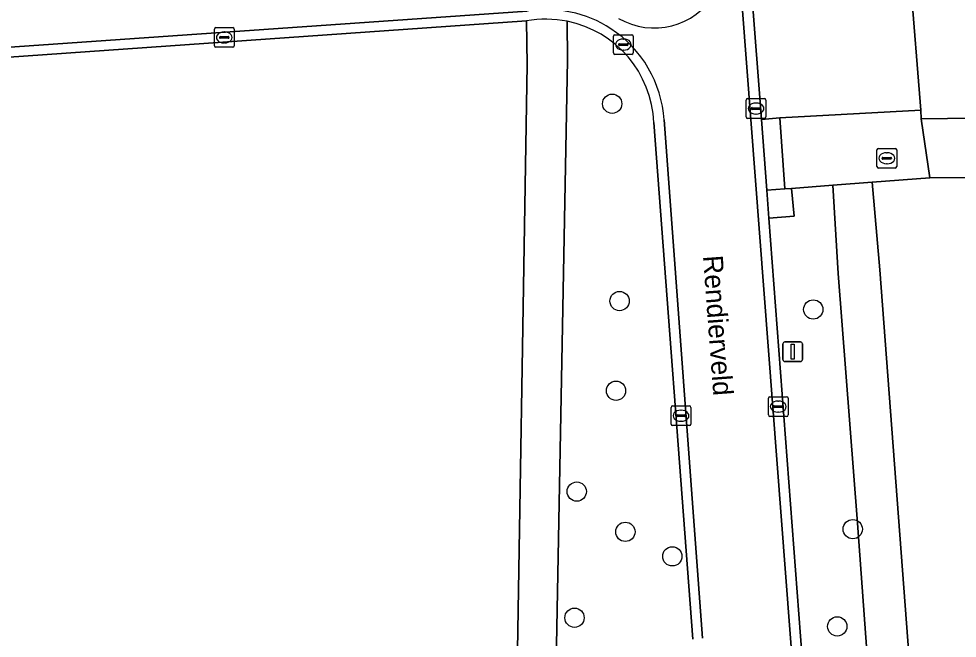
# Model space of a CAD drawing. Extents: x 162661 to 163484, y 380247 to 381230.
# Drawn here: x 163101.01 to 163148.58, y 380368.43 to 380399.85 of the extents above; entities that cross this region are included whole.
import ezdxf

# ---------------------------------------------------------------- set-up
doc = ezdxf.new("R2010")
doc.units = 0
for name, color, linetype in [('IMGEO_Berm_halfverhard', 7, 'Continuous'), ('IMGEO_Boom', 7, 'Continuous'), ('IMGEO_Erf', 7, 'Continuous'), ('IMGEO_Groenvoorziening', 7, 'Continuous'), ('IMGEO_Kolk', 7, 'Continuous'), ('IMGEO_Lichtmast', 7, 'Continuous'), ('IMGEO_Openbare_ruimte_label', 7, 'Continuous'), ('IMGEO_Parkeervlak_open', 7, 'Continuous'), ('IMGEO_Rijbaan_lokaal_gesloten', 7, 'Continuous'), ('IMGEO_Rijbaan_lokaal_open', 7, 'Continuous'), ('IMGEO_Rioolput', 7, 'Continuous'), ('IMGEO_Voetpad_open', 7, 'Continuous')]:
    doc.layers.add(name, color=color, linetype=linetype)

msp = doc.modelspace()

# ---------------------------------------------------------------- linework, layer by layer
at = {"layer": 'IMGEO_Berm_halfverhard'}
msp.add_lwpolyline([(163140.187, 380391.241), (163139.844, 380391.229), (163138.932, 380391.167), (163139.036, 380389.731), (163140.315, 380389.838)], close=True, dxfattribs=at)
at = {"layer": 'IMGEO_Boom'}
for centre in [(163131.093, 380395.542), (163131.467, 380385.535), (163141.285, 380385.108), (163131.287, 380380.986), (163129.297, 380375.871), (163131.762, 380373.827), (163143.288, 380373.966), (163134.141, 380372.586), (163129.184, 380369.472), (163142.501, 380369.033)]:
    msp.add_circle(centre, 0.489, dxfattribs=at)
at = {"layer": 'IMGEO_Erf'}
msp.add_lwpolyline([(163216.077, 380392.021), (163204.133, 380392.177), (163149.068, 380391.797), (163147.198, 380391.781), (163144.279, 380391.558), (163144.662, 380387.12), (163147.688, 380347.017), (163151.219, 380347.51), (163195.797, 380353.729), (163196.176, 380351.492), (163147.848, 380344.668), (163150.86, 380303.331), (163146.437, 380298.781)], dxfattribs=at)
at = {"layer": 'IMGEO_Groenvoorziening'}
for points in [[(163196.751, 380415.969), (163148.204, 380409.24), (163145.637, 380408.848), (163145.683, 380408.287), (163146.741, 380395.215), (163146.749, 380394.77), (163148.083, 380394.795), (163199.027, 380395.185)], [(163071.431, 380357.843), (163126.19, 380361.661), (163126.78, 380397.532), (163126.755, 380399.742), (163064.909, 380395.406)], [(163128.81, 380399.724), (163128.82, 380397.751), (163128.149, 380361.798), (163129.108, 380361.865)], [(163135.179, 380368.38), (163133.202, 380394.584)]]:
    msp.add_lwpolyline(points, dxfattribs=at)
msp.add_lwpolyline([(163142.548, 380386.928), (163142.283, 380391.415), (163140.187, 380391.241), (163140.315, 380389.838), (163139.036, 380389.731), (163142.33, 380346.217), (163145.542, 380346.659), (163143.52, 380374.274)], close=True, dxfattribs=at)
msp.add_arc((163127.737, 380394.36), 5.47, 2.3433, 78.6828, dxfattribs=at)
at = {"layer": 'IMGEO_Kolk'}
for p, q in [((163110.929, 380398.478), (163110.929, 380399.33)), ((163111.004, 380399.404), (163111.856, 380399.404)), ((163111.417, 380399.184), (163111.442, 380399.184)), ((163111.93, 380399.33), (163111.93, 380398.478)), ((163131.232, 380399.045), (163132.084, 380399.045)), ((163111.188, 380398.898), (163111.188, 380398.91)), ((163111.626, 380398.861), (163111.228, 380398.861)), ((163111.231, 380398.947), (163111.629, 380398.947)), ((163111.44, 380398.624), (163111.415, 380398.624)), ((163111.672, 380398.91), (163111.672, 380398.898)), ((163131.157, 380398.119), (163131.157, 380398.971)), ((163131.416, 380398.539), (163131.416, 380398.551)), ((163131.459, 380398.588), (163131.857, 380398.588)), ((163131.645, 380398.825), (163131.67, 380398.825)), ((163131.9, 380398.551), (163131.9, 380398.539)), ((163132.158, 380398.971), (163132.158, 380398.119)), ((163111.856, 380398.404), (163111.004, 380398.404)), ((163131.854, 380398.502), (163131.456, 380398.502)), ((163131.668, 380398.265), (163131.643, 380398.265)), ((163132.084, 380398.045), (163131.232, 380398.045)), ((163137.883, 380394.874), (163137.883, 380395.726)), ((163137.958, 380395.8), (163138.81, 380395.8)), ((163138.884, 380395.726), (163138.884, 380394.874)), ((163138.142, 380395.294), (163138.142, 380395.306)), ((163138.58, 380395.257), (163138.182, 380395.257)), ((163138.185, 380395.343), (163138.583, 380395.343)), ((163138.371, 380395.58), (163138.396, 380395.58)), ((163138.626, 380395.306), (163138.626, 380395.294)), ((163138.81, 380394.8), (163137.958, 380394.8)), ((163138.394, 380395.02), (163138.369, 380395.02)), ((163139.009, 380379.756), (163139.009, 380380.608)), ((163139.084, 380380.682), (163139.936, 380380.682)), ((163140.01, 380380.608), (163140.01, 380379.756)), ((163134.082, 380379.291), (163134.082, 380380.143)), ((163134.157, 380380.217), (163135.009, 380380.217)), ((163134.57, 380379.997), (163134.595, 380379.997)), ((163135.083, 380380.143), (163135.083, 380379.291)), ((163139.268, 380380.176), (163139.268, 380380.188)), ((163139.706, 380380.139), (163139.308, 380380.139)), ((163139.311, 380380.225), (163139.709, 380380.225)), ((163139.497, 380380.462), (163139.522, 380380.462)), ((163139.752, 380380.188), (163139.752, 380380.176)), ((163134.341, 380379.711), (163134.341, 380379.723)), ((163134.779, 380379.674), (163134.381, 380379.674)), ((163134.384, 380379.76), (163134.782, 380379.76)), ((163134.825, 380379.723), (163134.825, 380379.711)), ((163139.936, 380379.682), (163139.084, 380379.682)), ((163139.52, 380379.902), (163139.495, 380379.902)), ((163135.009, 380379.217), (163134.157, 380379.217)), ((163134.593, 380379.437), (163134.568, 380379.437))]:
    msp.add_line(p, q, dxfattribs=at)
for points in [[(163110.929, 380398.478), (163110.929, 380399.33)], [(163111.004, 380399.404), (163111.856, 380399.404)], [(163111.93, 380399.33), (163111.93, 380398.478)], [(163131.232, 380399.045), (163132.084, 380399.045)], [(163131.157, 380398.119), (163131.157, 380398.971)], [(163132.158, 380398.971), (163132.158, 380398.119)], [(163111.856, 380398.404), (163111.004, 380398.404)], [(163132.084, 380398.045), (163131.232, 380398.045)], [(163137.883, 380394.874), (163137.883, 380395.726)], [(163137.958, 380395.8), (163138.81, 380395.8)], [(163138.884, 380395.726), (163138.884, 380394.874)], [(163138.81, 380394.8), (163137.958, 380394.8)], [(163139.009, 380379.756), (163139.009, 380380.608)], [(163139.084, 380380.682), (163139.936, 380380.682)], [(163140.01, 380380.608), (163140.01, 380379.756)], [(163134.082, 380379.291), (163134.082, 380380.143)], [(163134.157, 380380.217), (163135.009, 380380.217)], [(163135.083, 380380.143), (163135.083, 380379.291)], [(163139.936, 380379.682), (163139.084, 380379.682)], [(163135.009, 380379.217), (163134.157, 380379.217)]]:
    msp.add_lwpolyline(points, dxfattribs=at)
for centre, radius, start, end in [((163111.006, 380399.328), 0.0765, 91.552, 178.448), ((163111.006, 380399.328), 0.0765, 91.552, 178.448), ((163111.854, 380399.328), 0.0765, 1.552, 88.448), ((163111.854, 380399.328), 0.0765, 1.552, 88.448), ((163131.234, 380398.969), 0.0765, 91.552, 178.448), ((163131.234, 380398.969), 0.0765, 91.552, 178.448), ((163132.082, 380398.969), 0.0765, 1.552, 88.448), ((163132.082, 380398.969), 0.0765, 1.552, 88.448), ((163111.228, 380398.907), 0.0403, 85.8775, 175.7526), ((163111.225, 380398.897), 0.0366, 178.938, 274.7102), ((163111.629, 380398.904), 0.043, 264.8664, 352.4533), ((163111.633, 380398.909), 0.0386, 1.7309, 96.639), ((163131.456, 380398.548), 0.0403, 85.8775, 175.7526), ((163131.861, 380398.55), 0.0386, 1.7309, 96.639), ((163111.006, 380398.48), 0.0765, 181.552, 268.448), ((163111.006, 380398.48), 0.0765, 181.552, 268.448), ((163111.854, 380398.48), 0.0765, 271.552, 358.448), ((163111.854, 380398.48), 0.0765, 271.552, 358.448), ((163131.234, 380398.121), 0.0765, 181.552, 268.448), ((163131.234, 380398.121), 0.0765, 181.552, 268.448), ((163131.453, 380398.538), 0.0366, 178.938, 274.7102), ((163131.857, 380398.545), 0.043, 264.8664, 352.4533), ((163132.082, 380398.121), 0.0765, 271.552, 358.448), ((163132.082, 380398.121), 0.0765, 271.552, 358.448), ((163137.96, 380395.724), 0.0765, 91.552, 178.448), ((163137.96, 380395.724), 0.0765, 91.552, 178.448), ((163138.808, 380395.724), 0.0765, 1.552, 88.448), ((163138.808, 380395.724), 0.0765, 1.552, 88.448), ((163138.182, 380395.303), 0.0403, 85.8775, 175.7526), ((163138.179, 380395.293), 0.0366, 178.938, 274.7102), ((163138.583, 380395.3), 0.043, 264.8664, 352.4533), ((163138.587, 380395.305), 0.0386, 1.7309, 96.639), ((163137.96, 380394.876), 0.0765, 181.552, 268.448), ((163137.96, 380394.876), 0.0765, 181.552, 268.448), ((163138.808, 380394.876), 0.0765, 271.552, 358.448), ((163138.808, 380394.876), 0.0765, 271.552, 358.448), ((163139.086, 380380.606), 0.0765, 91.552, 178.448), ((163139.086, 380380.606), 0.0765, 91.552, 178.448), ((163139.934, 380380.606), 0.0765, 1.552, 88.448), ((163139.934, 380380.606), 0.0765, 1.552, 88.448), ((163134.159, 380380.141), 0.0765, 91.552, 178.448), ((163134.159, 380380.141), 0.0765, 91.552, 178.448), ((163135.007, 380380.141), 0.0765, 1.552, 88.448), ((163135.007, 380380.141), 0.0765, 1.552, 88.448), ((163139.308, 380380.185), 0.0403, 85.8775, 175.7526), ((163139.305, 380380.175), 0.0366, 178.938, 274.7102), ((163139.709, 380380.182), 0.043, 264.8664, 352.4533), ((163139.713, 380380.187), 0.0386, 1.7309, 96.639), ((163134.381, 380379.72), 0.0403, 85.8775, 175.7526), ((163134.378, 380379.71), 0.0366, 178.938, 274.7102), ((163134.782, 380379.717), 0.043, 264.8664, 352.4533), ((163134.786, 380379.722), 0.0386, 1.7309, 96.639), ((163139.086, 380379.758), 0.0765, 181.552, 268.448), ((163139.086, 380379.758), 0.0765, 181.552, 268.448), ((163139.934, 380379.758), 0.0765, 271.552, 358.448), ((163139.934, 380379.758), 0.0765, 271.552, 358.448), ((163134.159, 380379.293), 0.0765, 181.552, 268.448), ((163134.159, 380379.293), 0.0765, 181.552, 268.448), ((163135.007, 380379.293), 0.0765, 271.552, 358.448), ((163135.007, 380379.293), 0.0765, 271.552, 358.448)]:
    msp.add_arc(centre, radius, start, end, dxfattribs=at)
for centre, major_axis, ratio, start_param, end_param in [((163111.416, 380398.904), (-0.387, 0.002), 0.722429, 4.712389, 7.853982), ((163111.441, 380398.904), (-0.39, 0.002), 0.717154, 1.570796, 4.712389), ((163131.644, 380398.545), (-0.387, 0.002), 0.722429, 4.712389, 7.853982), ((163131.669, 380398.545), (-0.39, 0.002), 0.717154, 1.570796, 4.712389), ((163138.37, 380395.3), (-0.387, 0.002), 0.722429, 4.712389, 7.853982), ((163138.395, 380395.3), (-0.39, 0.002), 0.717154, 1.570796, 4.712389), ((163134.569, 380379.717), (-0.387, 0.002), 0.722429, 4.712389, 7.853982), ((163134.594, 380379.717), (-0.39, 0.002), 0.717154, 1.570796, 4.712389), ((163139.496, 380380.182), (-0.387, 0.002), 0.722429, 4.712389, 7.853982), ((163139.521, 380380.182), (-0.39, 0.002), 0.717154, 1.570796, 4.712389)]:
    msp.add_ellipse(centre, major_axis=major_axis, ratio=ratio, start_param=start_param, end_param=end_param, dxfattribs=at)
at = {"layer": 'IMGEO_Lichtmast'}
for p, q in [((163139.749, 380382.565), (163139.749, 380383.365)), ((163139.749, 380383.365), (163139.749, 380382.565)), ((163139.849, 380383.465), (163140.639, 380383.465)), ((163140.639, 380383.465), (163139.849, 380383.465)), ((163140.739, 380383.365), (163140.739, 380382.565)), ((163140.739, 380382.565), (163140.739, 380383.365)), ((163140.639, 380382.465), (163139.849, 380382.465)), ((163139.849, 380382.465), (163140.639, 380382.465))]:
    msp.add_line(p, q, dxfattribs=at)
msp.add_lwpolyline([(163140.169, 380383.34), (163140.319, 380383.34), (163140.319, 380382.59), (163140.169, 380382.59), (163140.169, 380383.34)], dxfattribs=at)
for centre, start, end in [((163139.849, 380383.365), 90, 180), ((163139.849, 380383.365), 90, 180), ((163140.639, 380383.365), 0, 90), ((163140.639, 380383.365), 360, 90), ((163139.849, 380382.565), 180, 270), ((163139.849, 380382.565), 180, 270), ((163140.639, 380382.565), 270, 0), ((163140.639, 380382.565), 270, 0)]:
    msp.add_arc(centre, 0.1, start, end, dxfattribs=at)
at = {"layer": 'IMGEO_Parkeervlak_open'}
msp.add_lwpolyline([(163145.683, 380408.287), (163138.571, 380407.761), (163137.658, 380407.694), (163138.661, 380394.747), (163139.595, 380394.828), (163146.741, 380395.215)], close=True, dxfattribs=at)
at = {"layer": 'IMGEO_Rijbaan_lokaal_gesloten'}
for points in [[(163136.897, 380352.19), (163140.509, 380304.804), (163145.361, 380299.205), (163144.354, 380312.576), (163140.765, 380360.258), (163137.475, 380403.162), (163135.931, 380423.629), (163134.3, 380425.026)], [(163064.883, 380395.926), (163126.779, 380400.24), (163126.503, 380404.662)], [(163133.723, 380394.719), (163135.677, 380368.432)]]:
    msp.add_lwpolyline(points, dxfattribs=at)
for centre, radius, start, end in [((163133.224, 380402.985), 3.601, 239.7745, 328.8373), ((163127.761, 380394.35), 5.972, 56.8255, 99.4679), ((163127.754, 380394.343), 5.981, 3.6014, 56.796)]:
    msp.add_arc(centre, radius, start, end, dxfattribs=at)
at = {"layer": 'IMGEO_Rijbaan_lokaal_open'}
for points in [[(163135.931, 380423.629), (163137.475, 380403.162), (163140.765, 380360.258), (163144.354, 380312.576), (163144.858, 380312.613), (163143.776, 380327.092), (163143.705, 380328.045), (163143.26, 380333.996), (163142.987, 380337.579)], [(163142.987, 380337.579), (163142.503, 380343.939), (163142.33, 380346.217), (163139.036, 380389.731), (163138.932, 380391.167), (163138.661, 380394.747), (163137.658, 380407.694), (163137.378, 380411.312), (163137.292, 380412.726), (163136.528, 380422.373)], [(163126.779, 380400.24), (163064.883, 380395.926)], [(163064.909, 380395.406), (163126.755, 380399.742)], [(163133.202, 380394.584), (163135.179, 380368.38)], [(163135.677, 380368.432), (163133.723, 380394.719)]]:
    msp.add_lwpolyline(points, dxfattribs=at)
for centre, radius, start, end in [((163133.224, 380402.985), 3.601, 239.7745, 328.8373), ((163127.761, 380394.35), 5.972, 56.8255, 99.4679), ((163127.736, 380394.395), 5.436, 78.602, 100.3943), ((163127.737, 380394.36), 5.47, 2.3433, 78.6828), ((163127.754, 380394.343), 5.981, 3.6014, 56.796)]:
    msp.add_arc(centre, radius, start, end, dxfattribs=at)
at = {"layer": 'IMGEO_Rioolput'}
for p, q in [((163144.513, 380392.353), (163144.513, 380393.205)), ((163144.588, 380393.279), (163145.44, 380393.279)), ((163145.001, 380393.059), (163145.026, 380393.059)), ((163145.514, 380393.205), (163145.514, 380392.353)), ((163144.772, 380392.773), (163144.772, 380392.785)), ((163145.21, 380392.736), (163144.812, 380392.736)), ((163144.815, 380392.822), (163145.213, 380392.822)), ((163145.024, 380392.499), (163144.999, 380392.499)), ((163145.256, 380392.785), (163145.256, 380392.773)), ((163145.44, 380392.279), (163144.588, 380392.279))]:
    msp.add_line(p, q, dxfattribs=at)
for points in [[(163144.513, 380392.353), (163144.513, 380393.205)], [(163144.588, 380393.279), (163145.44, 380393.279)], [(163145.514, 380393.205), (163145.514, 380392.353)], [(163145.44, 380392.279), (163144.588, 380392.279)]]:
    msp.add_lwpolyline(points, dxfattribs=at)
for centre, radius, start, end in [((163144.59, 380393.203), 0.0765, 91.552, 178.448), ((163144.59, 380393.203), 0.0765, 91.552, 178.448), ((163145.438, 380393.203), 0.0765, 1.552, 88.448), ((163145.438, 380393.203), 0.0765, 1.552, 88.448), ((163144.812, 380392.782), 0.0403, 85.8775, 175.7526), ((163144.809, 380392.772), 0.0366, 178.938, 274.7102), ((163145.213, 380392.779), 0.043, 264.8664, 352.4533), ((163145.217, 380392.784), 0.0386, 1.7309, 96.639), ((163144.59, 380392.355), 0.0765, 181.552, 268.448), ((163144.59, 380392.355), 0.0765, 181.552, 268.448), ((163145.438, 380392.355), 0.0765, 271.552, 358.448), ((163145.438, 380392.355), 0.0765, 271.552, 358.448)]:
    msp.add_arc(centre, radius, start, end, dxfattribs=at)
for centre, major_axis, ratio, start_param, end_param in [((163145, 380392.779), (-0.387, 0.002), 0.722429, 4.712389, 7.853982), ((163145.025, 380392.779), (-0.39, 0.002), 0.717154, 1.570796, 4.712389)]:
    msp.add_ellipse(centre, major_axis=major_axis, ratio=ratio, start_param=start_param, end_param=end_param, dxfattribs=at)
at = {"layer": 'IMGEO_Voetpad_open'}
for points in [[(163199.027, 380395.185), (163148.083, 380394.795), (163146.749, 380394.77), (163147.198, 380391.781), (163149.068, 380391.797), (163204.133, 380392.177), (163201.407, 380419.631)], [(163126.755, 380399.742), (163126.78, 380397.532), (163126.19, 380361.661), (163128.149, 380361.798), (163128.82, 380397.751), (163128.81, 380399.724)], [(163147.688, 380347.017), (163144.662, 380387.12), (163144.279, 380391.558), (163142.283, 380391.415), (163142.548, 380386.928), (163143.52, 380374.274), (163145.542, 380346.659), (163145.702, 380344.371), (163146.161, 380337.725), (163146.382, 380334.519), (163146.812, 380328.289), (163143.705, 380328.045), (163143.776, 380327.092), (163146.94, 380327.36), (163147.986, 380312.918), (163144.858, 380312.613), (163144.927, 380311.69), (163148.051, 380312.02), (163148.492, 380305.927), (163146.45, 380305.736), (163145.326, 380306.355), (163145.856, 380299.256)]]:
    msp.add_lwpolyline(points, dxfattribs=at)
for points in [[(163139.844, 380391.229), (163139.595, 380394.828), (163138.661, 380394.747), (163138.932, 380391.167)], [(163146.749, 380394.77), (163146.741, 380395.215), (163139.595, 380394.828), (163139.844, 380391.229), (163140.187, 380391.241), (163142.283, 380391.415), (163144.279, 380391.558), (163147.198, 380391.781)]]:
    msp.add_lwpolyline(points, close=True, dxfattribs=at)
msp.add_arc((163127.736, 380394.395), 5.436, 78.602, 100.3943, dxfattribs=at)

# ---------------------------------------------------------------- texts
at = {"layer": 'IMGEO_Openbare_ruimte_label'}
msp.add_text('Rendierveld', height=1, rotation=274.2449, dxfattribs=at).set_placement((163135.695, 380387.821))

doc.saveas('drawing.dxf')
